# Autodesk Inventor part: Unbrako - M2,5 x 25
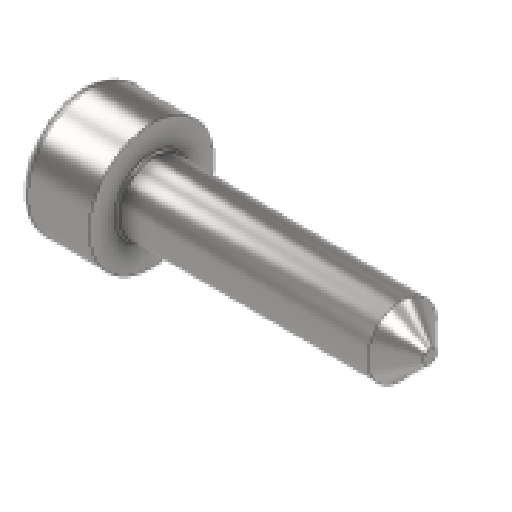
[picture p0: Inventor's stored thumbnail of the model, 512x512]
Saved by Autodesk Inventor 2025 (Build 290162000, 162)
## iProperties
Created: 2025-04
Part Number: Unbrako - M2,5 x 25
Material: Acciaio, Dolce
Description: Vite a testa cilindrica
Document SubType Name: Modeling
Designer: R5800u
Density: 7.85 g/cm^3
Appearance: Default
Sending System: Autodesk Inventor 2025
Preprocessor: ST-DEVELOPER v20
Title: autof - M3 x 8.stp
Author: R5800u
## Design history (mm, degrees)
feature "Solid1"
sketch "Schizzo1"
  geometry: C1 r 2.709 at (0, 0); 1 further point
  constraints: 1 centre point, 1 coincident
extrude "Estrusione1" cut sketch "Schizzo1" distance "d0" = 15; taper "d1" = 0 deg
chamfer "Smusso1" distance "d2" = 1; stored, may be unused: second distance "d3" = 2, angle "d4" = 45 deg
node "Solido1"
